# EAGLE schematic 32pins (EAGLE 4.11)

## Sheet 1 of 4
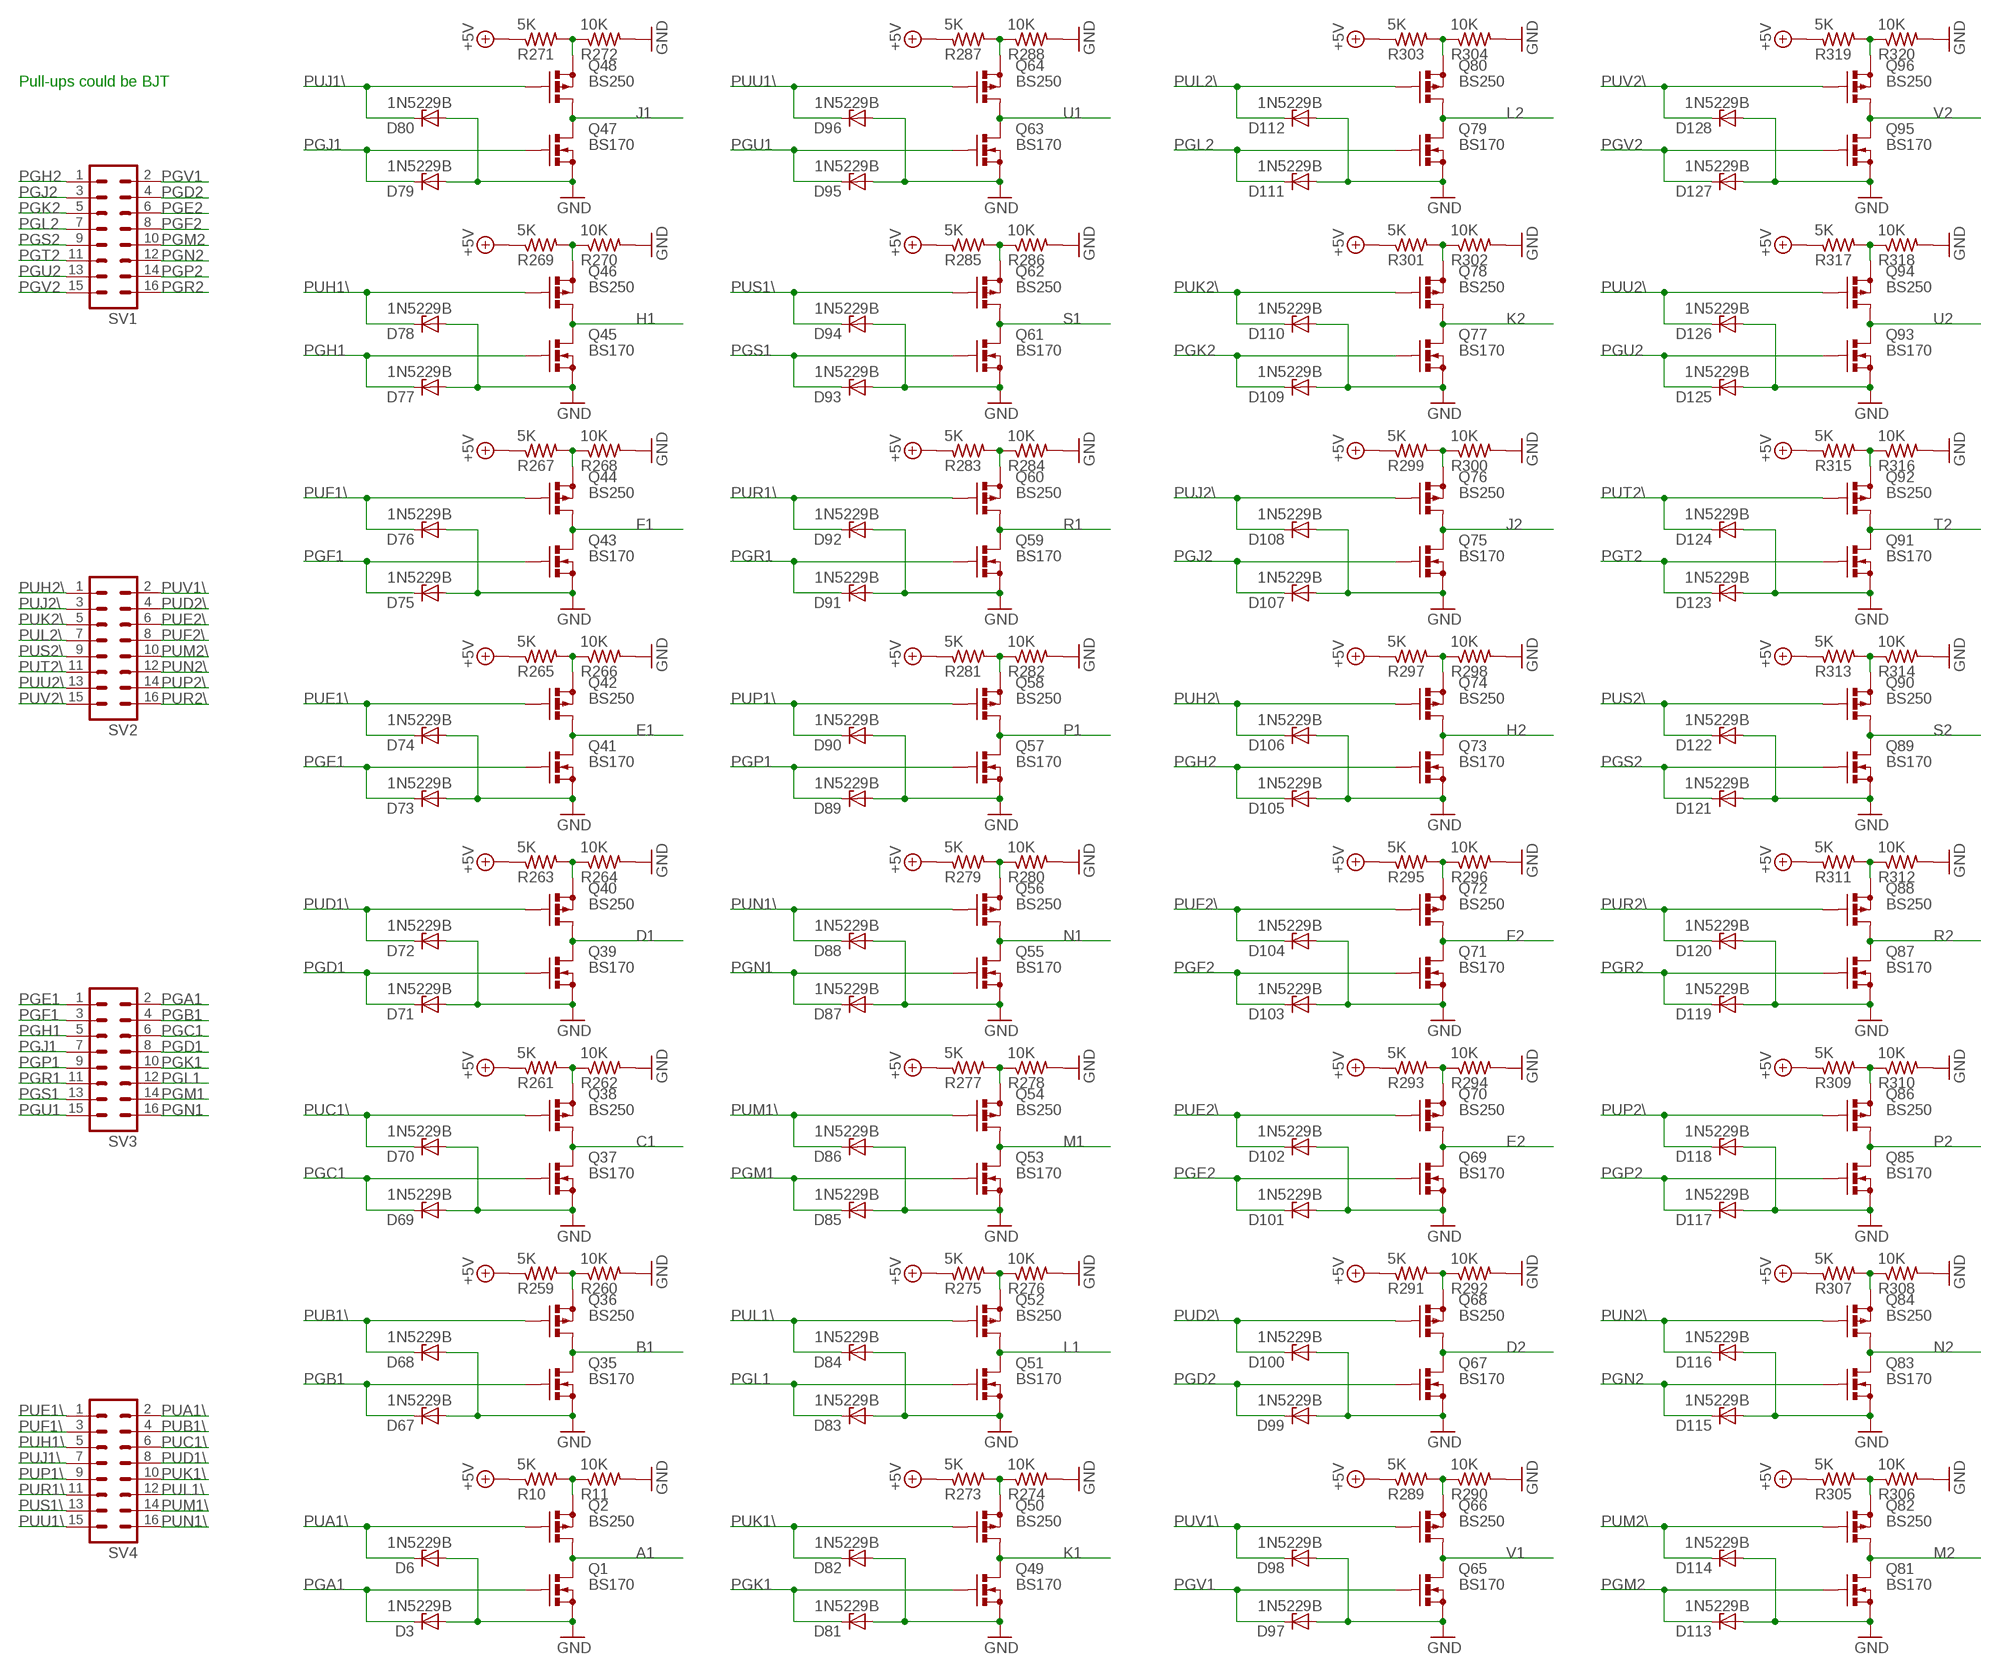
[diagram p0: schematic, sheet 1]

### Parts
D3  1N5229B  ZENER-DIODEZD-2.5  [ZDIO-2.5]
D6  1N5229B  ZENER-DIODEZD-2.5  [ZDIO-2.5]
D67  1N5229B  ZENER-DIODEZD-2.5  [ZDIO-2.5]
D68  1N5229B  ZENER-DIODEZD-2.5  [ZDIO-2.5]
D69  1N5229B  ZENER-DIODEZD-2.5  [ZDIO-2.5]
D70  1N5229B  ZENER-DIODEZD-2.5  [ZDIO-2.5]
D71  1N5229B  ZENER-DIODEZD-2.5  [ZDIO-2.5]
D72  1N5229B  ZENER-DIODEZD-2.5  [ZDIO-2.5]
D73  1N5229B  ZENER-DIODEZD-2.5  [ZDIO-2.5]
D74  1N5229B  ZENER-DIODEZD-2.5  [ZDIO-2.5]
D75  1N5229B  ZENER-DIODEZD-2.5  [ZDIO-2.5]
D76  1N5229B  ZENER-DIODEZD-2.5  [ZDIO-2.5]
D77  1N5229B  ZENER-DIODEZD-2.5  [ZDIO-2.5]
D78  1N5229B  ZENER-DIODEZD-2.5  [ZDIO-2.5]
D79  1N5229B  ZENER-DIODEZD-2.5  [ZDIO-2.5]
D80  1N5229B  ZENER-DIODEZD-2.5  [ZDIO-2.5]
D81  1N5229B  ZENER-DIODEZD-2.5  [ZDIO-2.5]
D82  1N5229B  ZENER-DIODEZD-2.5  [ZDIO-2.5]
D83  1N5229B  ZENER-DIODEZD-2.5  [ZDIO-2.5]
D84  1N5229B  ZENER-DIODEZD-2.5  [ZDIO-2.5]
D85  1N5229B  ZENER-DIODEZD-2.5  [ZDIO-2.5]
D86  1N5229B  ZENER-DIODEZD-2.5  [ZDIO-2.5]
D87  1N5229B  ZENER-DIODEZD-2.5  [ZDIO-2.5]
D88  1N5229B  ZENER-DIODEZD-2.5  [ZDIO-2.5]
D89  1N5229B  ZENER-DIODEZD-2.5  [ZDIO-2.5]
D90  1N5229B  ZENER-DIODEZD-2.5  [ZDIO-2.5]
D91  1N5229B  ZENER-DIODEZD-2.5  [ZDIO-2.5]
D92  1N5229B  ZENER-DIODEZD-2.5  [ZDIO-2.5]
D93  1N5229B  ZENER-DIODEZD-2.5  [ZDIO-2.5]
D94  1N5229B  ZENER-DIODEZD-2.5  [ZDIO-2.5]
D95  1N5229B  ZENER-DIODEZD-2.5  [ZDIO-2.5]
D96  1N5229B  ZENER-DIODEZD-2.5  [ZDIO-2.5]
D97  1N5229B  ZENER-DIODEZD-2.5  [ZDIO-2.5]
D98  1N5229B  ZENER-DIODEZD-2.5  [ZDIO-2.5]
D99  1N5229B  ZENER-DIODEZD-2.5  [ZDIO-2.5]
D100  1N5229B  ZENER-DIODEZD-2.5  [ZDIO-2.5]
D101  1N5229B  ZENER-DIODEZD-2.5  [ZDIO-2.5]
D102  1N5229B  ZENER-DIODEZD-2.5  [ZDIO-2.5]
D103  1N5229B  ZENER-DIODEZD-2.5  [ZDIO-2.5]
D104  1N5229B  ZENER-DIODEZD-2.5  [ZDIO-2.5]
D105  1N5229B  ZENER-DIODEZD-2.5  [ZDIO-2.5]
D106  1N5229B  ZENER-DIODEZD-2.5  [ZDIO-2.5]
D107  1N5229B  ZENER-DIODEZD-2.5  [ZDIO-2.5]
D108  1N5229B  ZENER-DIODEZD-2.5  [ZDIO-2.5]
D109  1N5229B  ZENER-DIODEZD-2.5  [ZDIO-2.5]
D110  1N5229B  ZENER-DIODEZD-2.5  [ZDIO-2.5]
D111  1N5229B  ZENER-DIODEZD-2.5  [ZDIO-2.5]
D112  1N5229B  ZENER-DIODEZD-2.5  [ZDIO-2.5]
D113  1N5229B  ZENER-DIODEZD-2.5  [ZDIO-2.5]
D114  1N5229B  ZENER-DIODEZD-2.5  [ZDIO-2.5]
D115  1N5229B  ZENER-DIODEZD-2.5  [ZDIO-2.5]
D116  1N5229B  ZENER-DIODEZD-2.5  [ZDIO-2.5]
D117  1N5229B  ZENER-DIODEZD-2.5  [ZDIO-2.5]
D118  1N5229B  ZENER-DIODEZD-2.5  [ZDIO-2.5]
D119  1N5229B  ZENER-DIODEZD-2.5  [ZDIO-2.5]
D120  1N5229B  ZENER-DIODEZD-2.5  [ZDIO-2.5]
D121  1N5229B  ZENER-DIODEZD-2.5  [ZDIO-2.5]
D122  1N5229B  ZENER-DIODEZD-2.5  [ZDIO-2.5]
D123  1N5229B  ZENER-DIODEZD-2.5  [ZDIO-2.5]
D124  1N5229B  ZENER-DIODEZD-2.5  [ZDIO-2.5]
D125  1N5229B  ZENER-DIODEZD-2.5  [ZDIO-2.5]
D126  1N5229B  ZENER-DIODEZD-2.5  [ZDIO-2.5]
D127  1N5229B  ZENER-DIODEZD-2.5  [ZDIO-2.5]
D128  1N5229B  ZENER-DIODEZD-2.5  [ZDIO-2.5]
Q1  BS170  [SOT54E]
Q2  BS250  [SOT54E]
Q35  BS170  [SOT54E]
Q36  BS250  [SOT54E]
Q37  BS170  [SOT54E]
Q38  BS250  [SOT54E]
Q39  BS170  [SOT54E]
Q40  BS250  [SOT54E]
Q41  BS170  [SOT54E]
Q42  BS250  [SOT54E]
Q43  BS170  [SOT54E]
Q44  BS250  [SOT54E]
Q45  BS170  [SOT54E]
Q46  BS250  [SOT54E]
Q47  BS170  [SOT54E]
Q48  BS250  [SOT54E]
Q49  BS170  [SOT54E]
Q50  BS250  [SOT54E]
Q51  BS170  [SOT54E]
Q52  BS250  [SOT54E]
Q53  BS170  [SOT54E]
Q54  BS250  [SOT54E]
Q55  BS170  [SOT54E]
Q56  BS250  [SOT54E]
Q57  BS170  [SOT54E]
Q58  BS250  [SOT54E]
Q59  BS170  [SOT54E]
Q60  BS250  [SOT54E]
Q61  BS170  [SOT54E]
Q62  BS250  [SOT54E]
Q63  BS170  [SOT54E]
Q64  BS250  [SOT54E]
Q65  BS170  [SOT54E]
Q66  BS250  [SOT54E]
Q67  BS170  [SOT54E]
Q68  BS250  [SOT54E]
Q69  BS170  [SOT54E]
Q70  BS250  [SOT54E]
Q71  BS170  [SOT54E]
Q72  BS250  [SOT54E]
Q73  BS170  [SOT54E]
Q74  BS250  [SOT54E]
Q75  BS170  [SOT54E]
Q76  BS250  [SOT54E]
Q77  BS170  [SOT54E]
Q78  BS250  [SOT54E]
Q79  BS170  [SOT54E]
Q80  BS250  [SOT54E]
Q81  BS170  [SOT54E]
Q82  BS250  [SOT54E]
Q83  BS170  [SOT54E]
Q84  BS250  [SOT54E]
Q85  BS170  [SOT54E]
Q86  BS250  [SOT54E]
Q87  BS170  [SOT54E]
Q88  BS250  [SOT54E]
Q89  BS170  [SOT54E]
Q90  BS250  [SOT54E]
Q91  BS170  [SOT54E]
Q92  BS250  [SOT54E]
Q93  BS170  [SOT54E]
Q94  BS250  [SOT54E]
Q95  BS170  [SOT54E]
Q96  BS250  [SOT54E]
R10  5K  R-US_0207/2V  [0207/2V]
R11  10K  R-US_0207/2V  [0207/2V]
R259  5K  R-US_0207/2V  [0207/2V]
R260  10K  R-US_0207/2V  [0207/2V]
R261  5K  R-US_0207/2V  [0207/2V]
R262  10K  R-US_0207/2V  [0207/2V]
R263  5K  R-US_0207/2V  [0207/2V]
R264  10K  R-US_0207/2V  [0207/2V]
R265  5K  R-US_0207/2V  [0207/2V]
R266  10K  R-US_0207/2V  [0207/2V]
R267  5K  R-US_0207/2V  [0207/2V]
R268  10K  R-US_0207/2V  [0207/2V]
R269  5K  R-US_0207/2V  [0207/2V]
R270  10K  R-US_0207/2V  [0207/2V]
R271  5K  R-US_0207/2V  [0207/2V]
R272  10K  R-US_0207/2V  [0207/2V]
R273  5K  R-US_0207/2V  [0207/2V]
R274  10K  R-US_0207/2V  [0207/2V]
R275  5K  R-US_0207/2V  [0207/2V]
R276  10K  R-US_0207/2V  [0207/2V]
R277  5K  R-US_0207/2V  [0207/2V]
R278  10K  R-US_0207/2V  [0207/2V]
R279  5K  R-US_0207/2V  [0207/2V]
R280  10K  R-US_0207/2V  [0207/2V]
R281  5K  R-US_0207/2V  [0207/2V]
R282  10K  R-US_0207/2V  [0207/2V]
R283  5K  R-US_0207/2V  [0207/2V]
R284  10K  R-US_0207/2V  [0207/2V]
R285  5K  R-US_0207/2V  [0207/2V]
R286  10K  R-US_0207/2V  [0207/2V]
R287  5K  R-US_0207/2V  [0207/2V]
R288  10K  R-US_0207/2V  [0207/2V]
R289  5K  R-US_0207/2V  [0207/2V]
R290  10K  R-US_0207/2V  [0207/2V]
R291  5K  R-US_0207/2V  [0207/2V]
R292  10K  R-US_0207/2V  [0207/2V]
R293  5K  R-US_0207/2V  [0207/2V]
R294  10K  R-US_0207/2V  [0207/2V]
R295  5K  R-US_0207/2V  [0207/2V]
R296  10K  R-US_0207/2V  [0207/2V]
R297  5K  R-US_0207/2V  [0207/2V]
R298  10K  R-US_0207/2V  [0207/2V]
R299  5K  R-US_0207/2V  [0207/2V]
R300  10K  R-US_0207/2V  [0207/2V]
R301  5K  R-US_0207/2V  [0207/2V]
R302  10K  R-US_0207/2V  [0207/2V]
R303  5K  R-US_0207/2V  [0207/2V]
R304  10K  R-US_0207/2V  [0207/2V]
R305  5K  R-US_0207/2V  [0207/2V]
R306  10K  R-US_0207/2V  [0207/2V]
R307  5K  R-US_0207/2V  [0207/2V]
R308  10K  R-US_0207/2V  [0207/2V]
R309  5K  R-US_0207/2V  [0207/2V]
R310  10K  R-US_0207/2V  [0207/2V]
R311  5K  R-US_0207/2V  [0207/2V]
R312  10K  R-US_0207/2V  [0207/2V]
R313  5K  R-US_0207/2V  [0207/2V]
R314  10K  R-US_0207/2V  [0207/2V]
R315  5K  R-US_0207/2V  [0207/2V]
R316  10K  R-US_0207/2V  [0207/2V]
R317  5K  R-US_0207/2V  [0207/2V]
R318  10K  R-US_0207/2V  [0207/2V]
R319  5K  R-US_0207/2V  [0207/2V]
R320  10K  R-US_0207/2V  [0207/2V]
SV1  MA08-2  [MA08-2]
SV2  MA08-2  [MA08-2]
SV3  MA08-2  [MA08-2]
SV4  MA08-2  [MA08-2]

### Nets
+5V: R10.1 R259.1 R261.1 R263.1 R265.1 R267.1 R269.1 R271.1 R273.1 R275.1 R277.1 R279.1 R281.1 R283.1 R285.1 R287.1 R289.1 R291.1 R293.1 R295.1 R297.1 R299.1 R301.1 R303.1 R305.1 R307.1 R309.1 R311.1 R313.1 R315.1 R317.1 R319.1 ; also sheet 4
A1: Q1.D Q2.D ; also sheet 2,3,4
B1: Q35.D Q36.D ; also sheet 2,3,4
C1: Q37.D Q38.D ; also sheet 2,3,4
D1: Q39.D Q40.D ; also sheet 2,3,4
D2: Q67.D Q68.D ; also sheet 2,3,4
E1: Q41.D Q42.D ; also sheet 2,3,4
E2: Q69.D Q70.D ; also sheet 2,3,4
F1: Q43.D Q44.D ; also sheet 2,3,4
F2: Q71.D Q72.D ; also sheet 2,3,4
GND: D3.A D6.A D67.A D68.A D69.A D70.A D71.A D72.A D73.A D74.A D75.A D76.A D77.A D78.A D79.A D80.A D81.A D82.A D83.A D84.A D85.A D86.A D87.A D88.A D89.A D90.A D91.A D92.A D93.A D94.A D95.A D96.A D97.A D98.A D99.A D100.A D101.A D102.A D103.A D104.A D105.A D106.A D107.A D108.A D109.A D110.A D111.A D112.A D113.A D114.A D115.A D116.A D117.A D118.A D119.A D120.A D121.A D122.A D123.A D124.A D125.A D126.A D127.A D128.A Q1.S Q35.S Q37.S Q39.S Q41.S Q43.S Q45.S Q47.S Q49.S Q51.S Q53.S Q55.S Q57.S Q59.S Q61.S Q63.S Q65.S Q67.S Q69.S Q71.S Q73.S Q75.S Q77.S Q79.S Q81.S Q83.S Q85.S Q87.S Q89.S Q91.S Q93.S Q95.S R11.2 R260.2 R262.2 R264.2 R266.2 R268.2 R270.2 R272.2 R274.2 R276.2 R278.2 R280.2 R282.2 R284.2 R286.2 R288.2 R290.2 R292.2 R294.2 R296.2 R298.2 R300.2 R302.2 R304.2 R306.2 R308.2 R310.2 R312.2 R314.2 R316.2 R318.2 R320.2 ; also sheet 2,3,4
H1: Q45.D Q46.D ; also sheet 2,3,4
H2: Q73.D Q74.D ; also sheet 2,3,4
J1: Q47.D Q48.D ; also sheet 2,3,4
J2: Q75.D Q76.D ; also sheet 2,3,4
K1: Q49.D Q50.D ; also sheet 2,3,4
K2: Q77.D Q78.D ; also sheet 2,3,4
L1: Q51.D Q52.D ; also sheet 2,3,4
L2: Q79.D Q80.D ; also sheet 2,3,4
M1: Q53.D Q54.D ; also sheet 2,3,4
M2: Q81.D Q82.D ; also sheet 2,3,4
N1: Q55.D Q56.D ; also sheet 2,3,4
N2: Q83.D Q84.D ; also sheet 2,3,4
N$5: Q2.S R10.2 R11.1
N$294: Q36.S R259.2 R260.1
N$298: Q38.S R261.2 R262.1
N$302: Q40.S R263.2 R264.1
N$306: Q42.S R265.2 R266.1
N$310: Q44.S R267.2 R268.1
N$314: Q46.S R269.2 R270.1
N$318: Q48.S R271.2 R272.1
N$322: Q50.S R273.2 R274.1
N$326: Q52.S R275.2 R276.1
N$330: Q54.S R277.2 R278.1
N$334: Q56.S R279.2 R280.1
N$338: Q58.S R281.2 R282.1
N$342: Q60.S R283.2 R284.1
N$346: Q62.S R285.2 R286.1
N$350: Q64.S R287.2 R288.1
N$354: Q66.S R289.2 R290.1
N$358: Q68.S R291.2 R292.1
N$362: Q70.S R293.2 R294.1
N$366: Q72.S R295.2 R296.1
N$370: Q74.S R297.2 R298.1
N$374: Q76.S R299.2 R300.1
N$378: Q78.S R301.2 R302.1
N$382: Q80.S R303.2 R304.1
N$386: Q82.S R305.2 R306.1
N$390: Q84.S R307.2 R308.1
N$394: Q86.S R309.2 R310.1
N$398: Q88.S R311.2 R312.1
N$402: Q90.S R313.2 R314.1
N$406: Q92.S R315.2 R316.1
N$410: Q94.S R317.2 R318.1
N$414: Q96.S R319.2 R320.1
P1: Q57.D Q58.D ; also sheet 2,3,4
P2: Q85.D Q86.D ; also sheet 2,3,4
PGA1: D3.C Q1.G SV3.2
PGB1: D67.C Q35.G SV3.4
PGC1: D69.C Q37.G SV3.6
PGD1: D71.C Q39.G SV3.8
PGD2: D99.C Q67.G SV1.4
PGE1: D73.C Q41.G SV3.1
PGE2: D101.C Q69.G SV1.6
PGF1: D75.C Q43.G SV3.3
PGF2: D103.C Q71.G SV1.8
PGH1: D77.C Q45.G SV3.5
PGH2: D105.C Q73.G SV1.1
PGJ1: D79.C Q47.G SV3.7
PGJ2: D107.C Q75.G SV1.3
PGK1: D81.C Q49.G SV3.10
PGK2: D109.C Q77.G SV1.5
PGL1: D83.C Q51.G SV3.12
PGL2: D111.C Q79.G SV1.7
PGM1: D85.C Q53.G SV3.14
PGM2: D113.C Q81.G SV1.10
PGN1: D87.C Q55.G SV3.16
PGN2: D115.C Q83.G SV1.12
PGP1: D89.C Q57.G SV3.9
PGP2: D117.C Q85.G SV1.14
PGR1: D91.C Q59.G SV3.11
PGR2: D119.C Q87.G SV1.16
PGS1: D93.C Q61.G SV3.13
PGS2: D121.C Q89.G SV1.9
PGT2: D123.C Q91.G SV1.11
PGU1: D95.C Q63.G SV3.15
PGU2: D125.C Q93.G SV1.13
PGV1: D97.C Q65.G SV1.2
PGV2: D127.C Q95.G SV1.15
PUA1\: D6.C Q2.G SV4.2
PUB1\: D68.C Q36.G SV4.4
PUC1\: D70.C Q38.G SV4.6
PUD1\: D72.C Q40.G SV4.8
PUD2\: D100.C Q68.G SV2.4
PUE1\: D74.C Q42.G SV4.1
PUE2\: D102.C Q70.G SV2.6
PUF1\: D76.C Q44.G SV4.3
PUF2\: D104.C Q72.G SV2.8
PUH1\: D78.C Q46.G SV4.5
PUH2\: D106.C Q74.G SV2.1
PUJ1\: D80.C Q48.G SV4.7
PUJ2\: D108.C Q76.G SV2.3
PUK1\: D82.C Q50.G SV4.10
PUK2\: D110.C Q78.G SV2.5
PUL1\: D84.C Q52.G SV4.12
PUL2\: D112.C Q80.G SV2.7
PUM1\: D86.C Q54.G SV4.14
PUM2\: D114.C Q82.G SV2.10
PUN1\: D88.C Q56.G SV4.16
PUN2\: D116.C Q84.G SV2.12
PUP1\: D90.C Q58.G SV4.9
PUP2\: D118.C Q86.G SV2.14
PUR1\: D92.C Q60.G SV4.11
PUR2\: D120.C Q88.G SV2.16
PUS1\: D94.C Q62.G SV4.13
PUS2\: D122.C Q90.G SV2.9
PUT2\: D124.C Q92.G SV2.11
PUU1\: D96.C Q64.G SV4.15
PUU2\: D126.C Q94.G SV2.13
PUV1\: D98.C Q66.G SV2.2
PUV2\: D128.C Q96.G SV2.15
R1: Q59.D Q60.D ; also sheet 2,3,4
R2: Q87.D Q88.D ; also sheet 2,3,4
S1: Q61.D Q62.D ; also sheet 2,3,4
S2: Q89.D Q90.D ; also sheet 2,3,4
T2: Q91.D Q92.D ; also sheet 2,3,4
U1: Q63.D Q64.D ; also sheet 2,3,4
U2: Q93.D Q94.D ; also sheet 2,3,4
V1: Q65.D Q66.D ; also sheet 2,3,4
V2: Q95.D Q96.D ; also sheet 2,3,4

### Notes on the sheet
- Pull-ups could be BJT

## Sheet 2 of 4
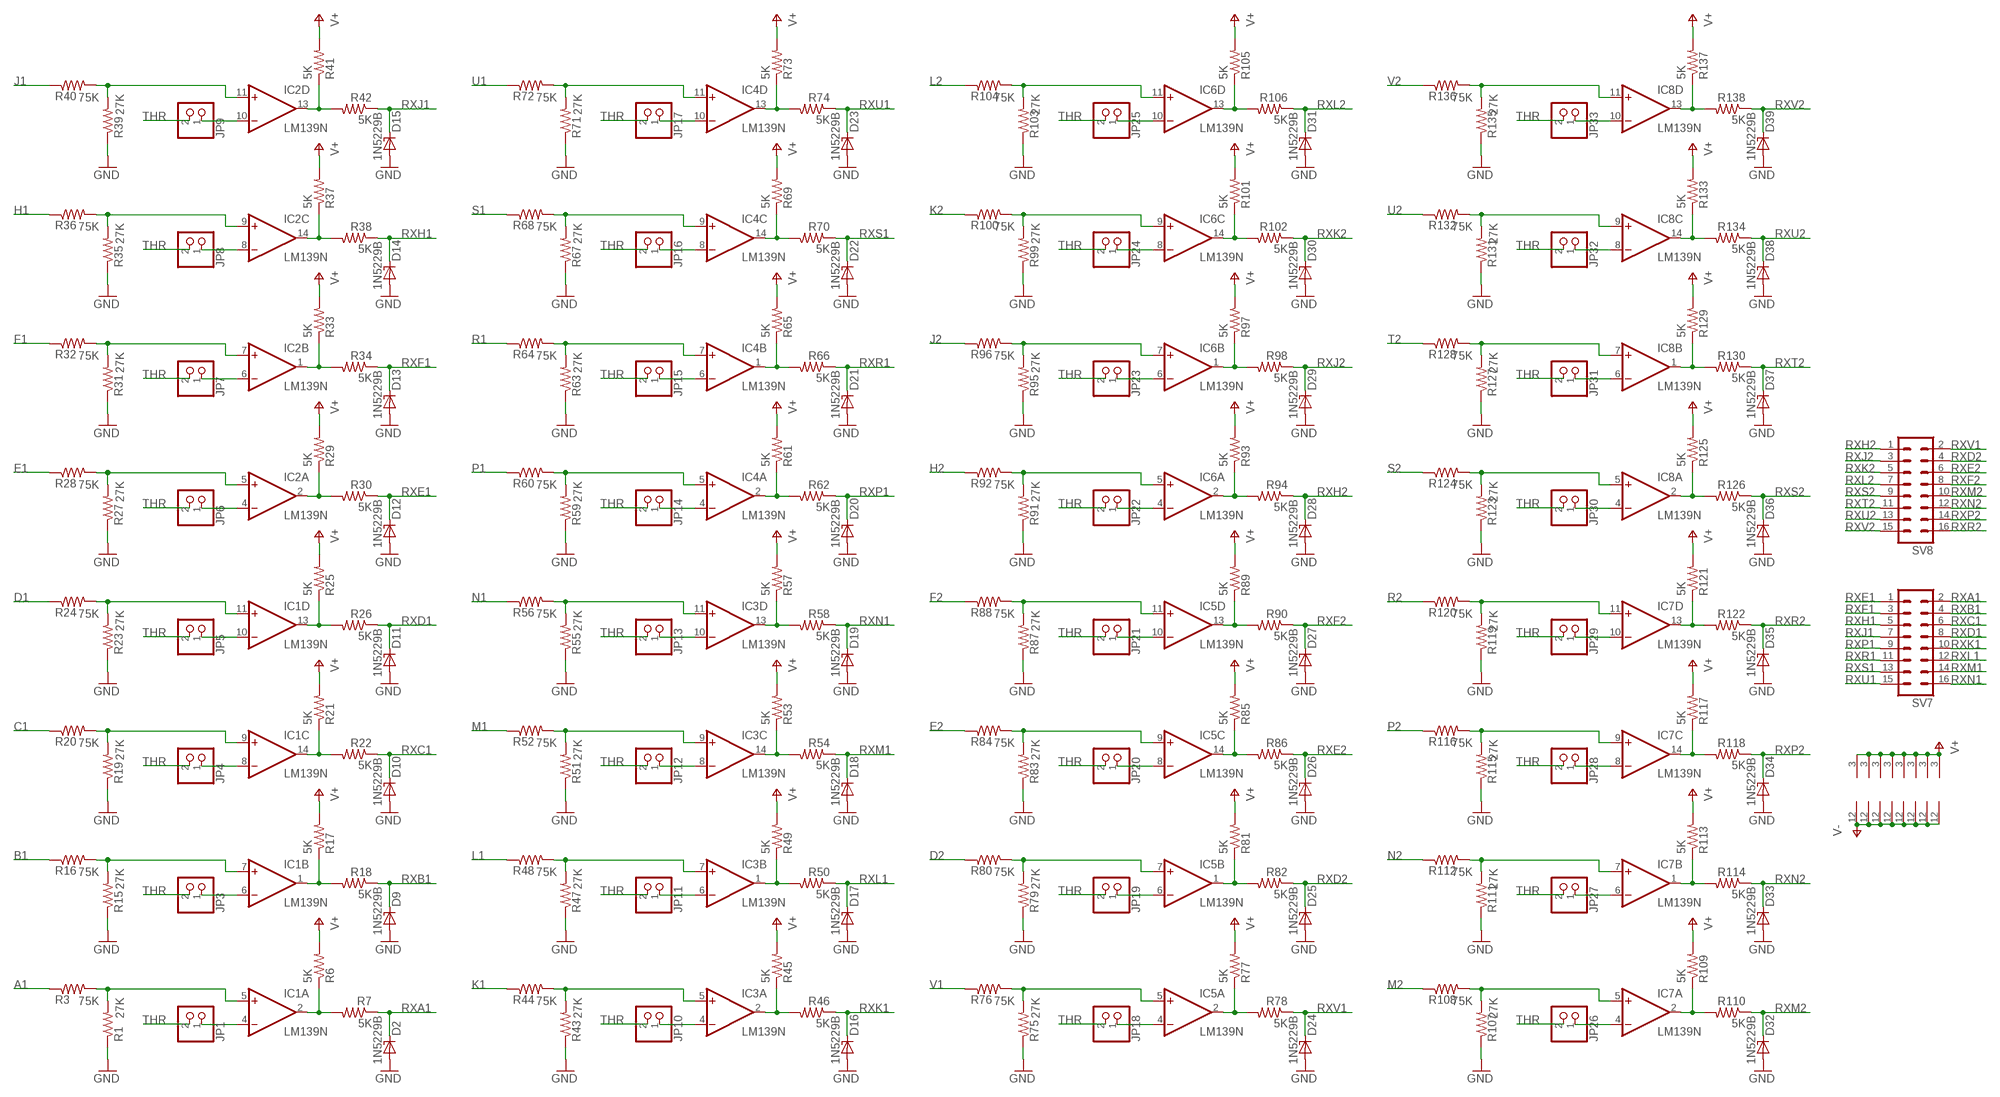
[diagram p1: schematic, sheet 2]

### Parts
D2  1N5229B  ZENER-DIODEZD-2.5  [ZDIO-2.5]
D9  1N5229B  ZENER-DIODEZD-2.5  [ZDIO-2.5]
D10  1N5229B  ZENER-DIODEZD-2.5  [ZDIO-2.5]
D11  1N5229B  ZENER-DIODEZD-2.5  [ZDIO-2.5]
D12  1N5229B  ZENER-DIODEZD-2.5  [ZDIO-2.5]
D13  1N5229B  ZENER-DIODEZD-2.5  [ZDIO-2.5]
D14  1N5229B  ZENER-DIODEZD-2.5  [ZDIO-2.5]
D15  1N5229B  ZENER-DIODEZD-2.5  [ZDIO-2.5]
D16  1N5229B  ZENER-DIODEZD-2.5  [ZDIO-2.5]
D17  1N5229B  ZENER-DIODEZD-2.5  [ZDIO-2.5]
D18  1N5229B  ZENER-DIODEZD-2.5  [ZDIO-2.5]
D19  1N5229B  ZENER-DIODEZD-2.5  [ZDIO-2.5]
D20  1N5229B  ZENER-DIODEZD-2.5  [ZDIO-2.5]
D21  1N5229B  ZENER-DIODEZD-2.5  [ZDIO-2.5]
D22  1N5229B  ZENER-DIODEZD-2.5  [ZDIO-2.5]
D23  1N5229B  ZENER-DIODEZD-2.5  [ZDIO-2.5]
D24  1N5229B  ZENER-DIODEZD-2.5  [ZDIO-2.5]
D25  1N5229B  ZENER-DIODEZD-2.5  [ZDIO-2.5]
D26  1N5229B  ZENER-DIODEZD-2.5  [ZDIO-2.5]
D27  1N5229B  ZENER-DIODEZD-2.5  [ZDIO-2.5]
D28  1N5229B  ZENER-DIODEZD-2.5  [ZDIO-2.5]
D29  1N5229B  ZENER-DIODEZD-2.5  [ZDIO-2.5]
D30  1N5229B  ZENER-DIODEZD-2.5  [ZDIO-2.5]
D31  1N5229B  ZENER-DIODEZD-2.5  [ZDIO-2.5]
D32  1N5229B  ZENER-DIODEZD-2.5  [ZDIO-2.5]
D33  1N5229B  ZENER-DIODEZD-2.5  [ZDIO-2.5]
D34  1N5229B  ZENER-DIODEZD-2.5  [ZDIO-2.5]
D35  1N5229B  ZENER-DIODEZD-2.5  [ZDIO-2.5]
D36  1N5229B  ZENER-DIODEZD-2.5  [ZDIO-2.5]
D37  1N5229B  ZENER-DIODEZD-2.5  [ZDIO-2.5]
D38  1N5229B  ZENER-DIODEZD-2.5  [ZDIO-2.5]
D39  1N5229B  ZENER-DIODEZD-2.5  [ZDIO-2.5]
IC1  LM139N  LM339N  [DIL14]
IC2  LM139N  LM339N  [DIL14]
IC3  LM139N  LM339N  [DIL14]
IC4  LM139N  LM339N  [DIL14]
IC5  LM139N  LM339N  [DIL14]
IC6  LM139N  LM339N  [DIL14]
IC7  LM139N  LM339N  [DIL14]
IC8  LM139N  LM339N  [DIL14]
JP1  PINHD-1X2  [1X02]
JP3  PINHD-1X2  [1X02]
JP4  PINHD-1X2  [1X02]
JP5  PINHD-1X2  [1X02]
JP6  PINHD-1X2  [1X02]
JP7  PINHD-1X2  [1X02]
JP8  PINHD-1X2  [1X02]
JP9  PINHD-1X2  [1X02]
JP10  PINHD-1X2  [1X02]
JP11  PINHD-1X2  [1X02]
JP12  PINHD-1X2  [1X02]
JP13  PINHD-1X2  [1X02]
JP14  PINHD-1X2  [1X02]
JP15  PINHD-1X2  [1X02]
JP16  PINHD-1X2  [1X02]
JP17  PINHD-1X2  [1X02]
JP18  PINHD-1X2  [1X02]
JP19  PINHD-1X2  [1X02]
JP20  PINHD-1X2  [1X02]
JP21  PINHD-1X2  [1X02]
JP22  PINHD-1X2  [1X02]
JP23  PINHD-1X2  [1X02]
JP24  PINHD-1X2  [1X02]
JP25  PINHD-1X2  [1X02]
JP26  PINHD-1X2  [1X02]
JP27  PINHD-1X2  [1X02]
JP28  PINHD-1X2  [1X02]
JP29  PINHD-1X2  [1X02]
JP30  PINHD-1X2  [1X02]
JP31  PINHD-1X2  [1X02]
JP32  PINHD-1X2  [1X02]
JP33  PINHD-1X2  [1X02]
R1  27K  R-US_0207/2V  [0207/2V]
R3  75K  R-US_0207/2V  [0207/2V]
R6  5K  R-US_0207/2V  [0207/2V]
R7  5K  R-US_0207/2V  [0207/2V]
R15  27K  R-US_0207/2V  [0207/2V]
R16  75K  R-US_0207/2V  [0207/2V]
R17  5K  R-US_0207/2V  [0207/2V]
R18  5K  R-US_0207/2V  [0207/2V]
R19  27K  R-US_0207/2V  [0207/2V]
R20  75K  R-US_0207/2V  [0207/2V]
R21  5K  R-US_0207/2V  [0207/2V]
R22  5K  R-US_0207/2V  [0207/2V]
R23  27K  R-US_0207/2V  [0207/2V]
R24  75K  R-US_0207/2V  [0207/2V]
R25  5K  R-US_0207/2V  [0207/2V]
R26  5K  R-US_0207/2V  [0207/2V]
R27  27K  R-US_0207/2V  [0207/2V]
R28  75K  R-US_0207/2V  [0207/2V]
R29  5K  R-US_0207/2V  [0207/2V]
R30  5K  R-US_0207/2V  [0207/2V]
R31  27K  R-US_0207/2V  [0207/2V]
R32  75K  R-US_0207/2V  [0207/2V]
R33  5K  R-US_0207/2V  [0207/2V]
R34  5K  R-US_0207/2V  [0207/2V]
R35  27K  R-US_0207/2V  [0207/2V]
R36  75K  R-US_0207/2V  [0207/2V]
R37  5K  R-US_0207/2V  [0207/2V]
R38  5K  R-US_0207/2V  [0207/2V]
R39  27K  R-US_0207/2V  [0207/2V]
R40  75K  R-US_0207/2V  [0207/2V]
R41  5K  R-US_0207/2V  [0207/2V]
R42  5K  R-US_0207/2V  [0207/2V]
R43  27K  R-US_0207/2V  [0207/2V]
R44  75K  R-US_0207/2V  [0207/2V]
R45  5K  R-US_0207/2V  [0207/2V]
R46  5K  R-US_0207/2V  [0207/2V]
R47  27K  R-US_0207/2V  [0207/2V]
R48  75K  R-US_0207/2V  [0207/2V]
R49  5K  R-US_0207/2V  [0207/2V]
R50  5K  R-US_0207/2V  [0207/2V]
R51  27K  R-US_0207/2V  [0207/2V]
R52  75K  R-US_0207/2V  [0207/2V]
R53  5K  R-US_0207/2V  [0207/2V]
R54  5K  R-US_0207/2V  [0207/2V]
R55  27K  R-US_0207/2V  [0207/2V]
R56  75K  R-US_0207/2V  [0207/2V]
R57  5K  R-US_0207/2V  [0207/2V]
R58  5K  R-US_0207/2V  [0207/2V]
R59  27K  R-US_0207/2V  [0207/2V]
R60  75K  R-US_0207/2V  [0207/2V]
R61  5K  R-US_0207/2V  [0207/2V]
R62  5K  R-US_0207/2V  [0207/2V]
R63  27K  R-US_0207/2V  [0207/2V]
R64  75K  R-US_0207/2V  [0207/2V]
R65  5K  R-US_0207/2V  [0207/2V]
R66  5K  R-US_0207/2V  [0207/2V]
R67  27K  R-US_0207/2V  [0207/2V]
R68  75K  R-US_0207/2V  [0207/2V]
R69  5K  R-US_0207/2V  [0207/2V]
R70  5K  R-US_0207/2V  [0207/2V]
R71  27K  R-US_0207/2V  [0207/2V]
R72  75K  R-US_0207/2V  [0207/2V]
R73  5K  R-US_0207/2V  [0207/2V]
R74  5K  R-US_0207/2V  [0207/2V]
R75  27K  R-US_0207/2V  [0207/2V]
R76  75K  R-US_0207/2V  [0207/2V]
R77  5K  R-US_0207/2V  [0207/2V]
R78  5K  R-US_0207/2V  [0207/2V]
R79  27K  R-US_0207/2V  [0207/2V]
R80  75K  R-US_0207/2V  [0207/2V]
R81  5K  R-US_0207/2V  [0207/2V]
R82  5K  R-US_0207/2V  [0207/2V]
R83  27K  R-US_0207/2V  [0207/2V]
R84  75K  R-US_0207/2V  [0207/2V]
R85  5K  R-US_0207/2V  [0207/2V]
R86  5K  R-US_0207/2V  [0207/2V]
R87  27K  R-US_0207/2V  [0207/2V]
R88  75K  R-US_0207/2V  [0207/2V]
R89  5K  R-US_0207/2V  [0207/2V]
R90  5K  R-US_0207/2V  [0207/2V]
R91  27K  R-US_0207/2V  [0207/2V]
R92  75K  R-US_0207/2V  [0207/2V]
R93  5K  R-US_0207/2V  [0207/2V]
R94  5K  R-US_0207/2V  [0207/2V]
R95  27K  R-US_0207/2V  [0207/2V]
R96  75K  R-US_0207/2V  [0207/2V]
R97  5K  R-US_0207/2V  [0207/2V]
R98  5K  R-US_0207/2V  [0207/2V]
R99  27K  R-US_0207/2V  [0207/2V]
R100  75K  R-US_0207/2V  [0207/2V]
R101  5K  R-US_0207/2V  [0207/2V]
R102  5K  R-US_0207/2V  [0207/2V]
R103  27K  R-US_0207/2V  [0207/2V]
R104  75K  R-US_0207/2V  [0207/2V]
R105  5K  R-US_0207/2V  [0207/2V]
R106  5K  R-US_0207/2V  [0207/2V]
R107  27K  R-US_0207/2V  [0207/2V]
R108  75K  R-US_0207/2V  [0207/2V]
R109  5K  R-US_0207/2V  [0207/2V]
R110  5K  R-US_0207/2V  [0207/2V]
R111  27K  R-US_0207/2V  [0207/2V]
R112  75K  R-US_0207/2V  [0207/2V]
R113  5K  R-US_0207/2V  [0207/2V]
R114  5K  R-US_0207/2V  [0207/2V]
R115  27K  R-US_0207/2V  [0207/2V]
R116  75K  R-US_0207/2V  [0207/2V]
R117  5K  R-US_0207/2V  [0207/2V]
R118  5K  R-US_0207/2V  [0207/2V]
R119  27K  R-US_0207/2V  [0207/2V]
R120  75K  R-US_0207/2V  [0207/2V]
R121  5K  R-US_0207/2V  [0207/2V]
R122  5K  R-US_0207/2V  [0207/2V]
R123  27K  R-US_0207/2V  [0207/2V]
R124  75K  R-US_0207/2V  [0207/2V]
R125  5K  R-US_0207/2V  [0207/2V]
R126  5K  R-US_0207/2V  [0207/2V]
R127  27K  R-US_0207/2V  [0207/2V]
R128  75K  R-US_0207/2V  [0207/2V]
R129  5K  R-US_0207/2V  [0207/2V]
R130  5K  R-US_0207/2V  [0207/2V]
R131  27K  R-US_0207/2V  [0207/2V]
R132  75K  R-US_0207/2V  [0207/2V]
R133  5K  R-US_0207/2V  [0207/2V]
R134  5K  R-US_0207/2V  [0207/2V]
R135  27K  R-US_0207/2V  [0207/2V]
R136  75K  R-US_0207/2V  [0207/2V]
R137  5K  R-US_0207/2V  [0207/2V]
R138  5K  R-US_0207/2V  [0207/2V]
SV7  MA08-2  [MA08-2]
SV8  MA08-2  [MA08-2]

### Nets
A1: R3.1 ; also sheet 1,3,4
B1: R16.1 ; also sheet 1,3,4
C1: R20.1 ; also sheet 1,3,4
D1: R24.1 ; also sheet 1,3,4
D2: R80.1 ; also sheet 1,3,4
E1: R28.1 ; also sheet 1,3,4
E2: R84.1 ; also sheet 1,3,4
F1: R32.1 ; also sheet 1,3,4
F2: R88.1 ; also sheet 1,3,4
GND: D2.A D9.A D10.A D11.A D12.A D13.A D14.A D15.A D16.A D17.A D18.A D19.A D20.A D21.A D22.A D23.A D24.A D25.A D26.A D27.A D28.A D29.A D30.A D31.A D32.A D33.A D34.A D35.A D36.A D37.A D38.A D39.A R1.1 R15.1 R19.1 R23.1 R27.1 R31.1 R35.1 R39.1 R43.1 R47.1 R51.1 R55.1 R59.1 R63.1 R67.1 R71.1 R75.1 R79.1 R83.1 R87.1 R91.1 R95.1 R99.1 R103.1 R107.1 R111.1 R115.1 R119.1 R123.1 R127.1 R131.1 R135.1 ; also sheet 1,3,4
H1: R36.1 ; also sheet 1,3,4
H2: R92.1 ; also sheet 1,3,4
J1: R40.1 ; also sheet 1,3,4
J2: R96.1 ; also sheet 1,3,4
K1: R44.1 ; also sheet 1,3,4
K2: R100.1 ; also sheet 1,3,4
L1: R48.1 ; also sheet 1,3,4
L2: R104.1 ; also sheet 1,3,4
M1: R52.1 ; also sheet 1,3,4
M2: R108.1 ; also sheet 1,3,4
N1: R56.1 ; also sheet 1,3,4
N2: R112.1 ; also sheet 1,3,4
N$13: IC1.5(A:+IN) R1.2 R3.2
N$14: IC1.4(A:-IN) JP1.1
N$18: IC1.2(A:OUT) R6.1 R7.2
N$20: IC1.7(B:+IN) R15.2 R16.2
N$21: IC1.6(B:-IN) JP3.1
N$22: IC1.1(B:OUT) R17.1 R18.2
N$23: IC1.9(C:+IN) R19.2 R20.2
N$24: IC1.8(C:-IN) JP4.1
N$25: IC1.14(C:OUT) R21.1 R22.2
N$26: IC1.11(D:+IN) R23.2 R24.2
N$27: IC1.10(D:-IN) JP5.1
N$28: IC1.13(D:OUT) R25.1 R26.2
N$35: IC2.5(A:+IN) R27.2 R28.2
N$36: IC2.4(A:-IN) JP6.1
N$38: IC2.2(A:OUT) R29.1 R30.2
N$39: IC2.7(B:+IN) R31.2 R32.2
N$40: IC2.6(B:-IN) JP7.1
N$41: IC2.1(B:OUT) R33.1 R34.2
N$42: IC2.9(C:+IN) R35.2 R36.2
N$43: IC2.8(C:-IN) JP8.1
N$44: IC2.14(C:OUT) R37.1 R38.2
N$45: IC2.11(D:+IN) R39.2 R40.2
N$46: IC2.10(D:-IN) JP9.1
N$47: IC2.13(D:OUT) R41.1 R42.2
N$55: IC3.5(A:+IN) R43.2 R44.2
N$56: IC3.4(A:-IN) JP10.1
N$58: IC3.2(A:OUT) R45.1 R46.2
N$59: IC3.7(B:+IN) R47.2 R48.2
N$60: IC3.6(B:-IN) JP11.1
N$61: IC3.1(B:OUT) R49.1 R50.2
N$62: IC3.9(C:+IN) R51.2 R52.2
N$63: IC3.8(C:-IN) JP12.1
N$64: IC3.14(C:OUT) R53.1 R54.2
N$65: IC3.11(D:+IN) R55.2 R56.2
N$66: IC3.10(D:-IN) JP13.1
N$67: IC3.13(D:OUT) R57.1 R58.2
N$75: IC4.5(A:+IN) R59.2 R60.2
N$76: IC4.4(A:-IN) JP14.1
N$78: IC4.2(A:OUT) R61.1 R62.2
N$79: IC4.7(B:+IN) R63.2 R64.2
N$80: IC4.6(B:-IN) JP15.1
N$81: IC4.1(B:OUT) R65.1 R66.2
N$82: IC4.9(C:+IN) R67.2 R68.2
N$83: IC4.8(C:-IN) JP16.1
N$84: IC4.14(C:OUT) R69.1 R70.2
N$85: IC4.11(D:+IN) R71.2 R72.2
N$86: IC4.10(D:-IN) JP17.1
N$87: IC4.13(D:OUT) R73.1 R74.2
N$95: IC5.5(A:+IN) R75.2 R76.2
N$96: IC5.4(A:-IN) JP18.1
N$98: IC5.2(A:OUT) R77.1 R78.2
N$99: IC5.7(B:+IN) R79.2 R80.2
N$100: IC5.6(B:-IN) JP19.1
N$101: IC5.1(B:OUT) R81.1 R82.2
N$102: IC5.9(C:+IN) R83.2 R84.2
N$103: IC5.8(C:-IN) JP20.1
N$104: IC5.14(C:OUT) R85.1 R86.2
N$105: IC5.11(D:+IN) R87.2 R88.2
N$106: IC5.10(D:-IN) JP21.1
N$107: IC5.13(D:OUT) R89.1 R90.2
N$115: IC6.5(A:+IN) R91.2 R92.2
N$116: IC6.4(A:-IN) JP22.1
N$118: IC6.2(A:OUT) R93.1 R94.2
N$119: IC6.7(B:+IN) R95.2 R96.2
N$120: IC6.6(B:-IN) JP23.1
N$121: IC6.1(B:OUT) R97.1 R98.2
N$122: IC6.9(C:+IN) R99.2 R100.2
N$123: IC6.8(C:-IN) JP24.1
N$124: IC6.14(C:OUT) R101.1 R102.2
N$125: IC6.11(D:+IN) R103.2 R104.2
N$126: IC6.10(D:-IN) JP25.1
N$127: IC6.13(D:OUT) R105.1 R106.2
N$135: IC7.5(A:+IN) R107.2 R108.2
N$136: IC7.4(A:-IN) JP26.1
N$138: IC7.2(A:OUT) R109.1 R110.2
N$139: IC7.7(B:+IN) R111.2 R112.2
N$140: IC7.6(B:-IN) JP27.1
N$141: IC7.1(B:OUT) R113.1 R114.2
N$142: IC7.9(C:+IN) R115.2 R116.2
N$143: IC7.8(C:-IN) JP28.1
N$144: IC7.14(C:OUT) R117.1 R118.2
N$145: IC7.11(D:+IN) R119.2 R120.2
N$146: IC7.10(D:-IN) JP29.1
N$147: IC7.13(D:OUT) R121.1 R122.2
N$155: IC8.5(A:+IN) R123.2 R124.2
N$156: IC8.4(A:-IN) JP30.1
N$158: IC8.2(A:OUT) R125.1 R126.2
N$159: IC8.7(B:+IN) R127.2 R128.2
N$160: IC8.6(B:-IN) JP31.1
N$161: IC8.1(B:OUT) R129.1 R130.2
N$162: IC8.9(C:+IN) R131.2 R132.2
N$163: IC8.8(C:-IN) JP32.1
N$164: IC8.14(C:OUT) R133.1 R134.2
N$165: IC8.11(D:+IN) R135.2 R136.2
N$166: IC8.10(D:-IN) JP33.1
N$167: IC8.13(D:OUT) R137.1 R138.2
P1: R60.1 ; also sheet 1,3,4
P2: R116.1 ; also sheet 1,3,4
R1: R64.1 ; also sheet 1,3,4
R2: R120.1 ; also sheet 1,3,4
RXA1: D2.C R7.1 SV7.2
RXB1: D9.C R18.1 SV7.4
RXC1: D10.C R22.1 SV7.6
RXD1: D11.C R26.1 SV7.8
RXD2: D25.C R82.1 SV8.4
RXE1: D12.C R30.1 SV7.1
RXE2: D26.C R86.1 SV8.6
RXF1: D13.C R34.1 SV7.3
RXF2: D27.C R90.1 SV8.8
RXH1: D14.C R38.1 SV7.5
RXH2: D28.C R94.1 SV8.1
RXJ1: D15.C R42.1 SV7.7
RXJ2: D29.C R98.1 SV8.3
RXK1: D16.C R46.1 SV7.10
RXK2: D30.C R102.1 SV8.5
RXL1: D17.C R50.1 SV7.12
RXL2: D31.C R106.1 SV8.7
RXM1: D18.C R54.1 SV7.14
RXM2: D32.C R110.1 SV8.10
RXN1: D19.C R58.1 SV7.16
RXN2: D33.C R114.1 SV8.12
RXP1: D20.C R62.1 SV7.9
RXP2: D34.C R118.1 SV8.14
RXR1: D21.C R66.1 SV7.11
RXR2: D35.C R122.1 SV8.16
RXS1: D22.C R70.1 SV7.13
RXS2: D36.C R126.1 SV8.9
RXT2: D37.C R130.1 SV8.11
RXU1: D23.C R74.1 SV7.15
RXU2: D38.C R134.1 SV8.13
RXV1: D24.C R78.1 SV8.2
RXV2: D39.C R138.1 SV8.15
S1: R68.1 ; also sheet 1,3,4
S2: R124.1 ; also sheet 1,3,4
T2: R128.1 ; also sheet 1,3,4
THR: JP1.2 JP3.2 JP4.2 JP5.2 JP6.2 JP7.2 JP8.2 JP9.2 JP10.2 JP11.2 JP12.2 JP13.2 JP14.2 JP15.2 JP16.2 JP17.2 JP18.2 JP19.2 JP20.2 JP21.2 JP22.2 JP23.2 JP24.2 JP25.2 JP26.2 JP27.2 JP28.2 JP29.2 JP30.2 JP31.2 JP32.2 JP33.2 ; also sheet 4
U1: R72.1 ; also sheet 1,3,4
U2: R132.1 ; also sheet 1,3,4
V1: R76.1 ; also sheet 1,3,4
V2: R136.1 ; also sheet 1,3,4
V+: IC1.3(P:V+) IC2.3(P:V+) IC3.3(P:V+) IC4.3(P:V+) IC5.3(P:V+) IC6.3(P:V+) IC7.3(P:V+) IC8.3(P:V+) R6.2 R17.2 R21.2 R25.2 R29.2 R33.2 R37.2 R41.2 R45.2 R49.2 R53.2 R57.2 R61.2 R65.2 R69.2 R73.2 R77.2 R81.2 R85.2 R89.2 R93.2 R97.2 R101.2 R105.2 R109.2 R113.2 R117.2 R121.2 R125.2 R129.2 R133.2 R137.2 ; also sheet 4
V-: IC1.12(P:GND) IC2.12(P:GND) IC3.12(P:GND) IC4.12(P:GND) IC5.12(P:GND) IC6.12(P:GND) IC7.12(P:GND) IC8.12(P:GND) ; also sheet 4

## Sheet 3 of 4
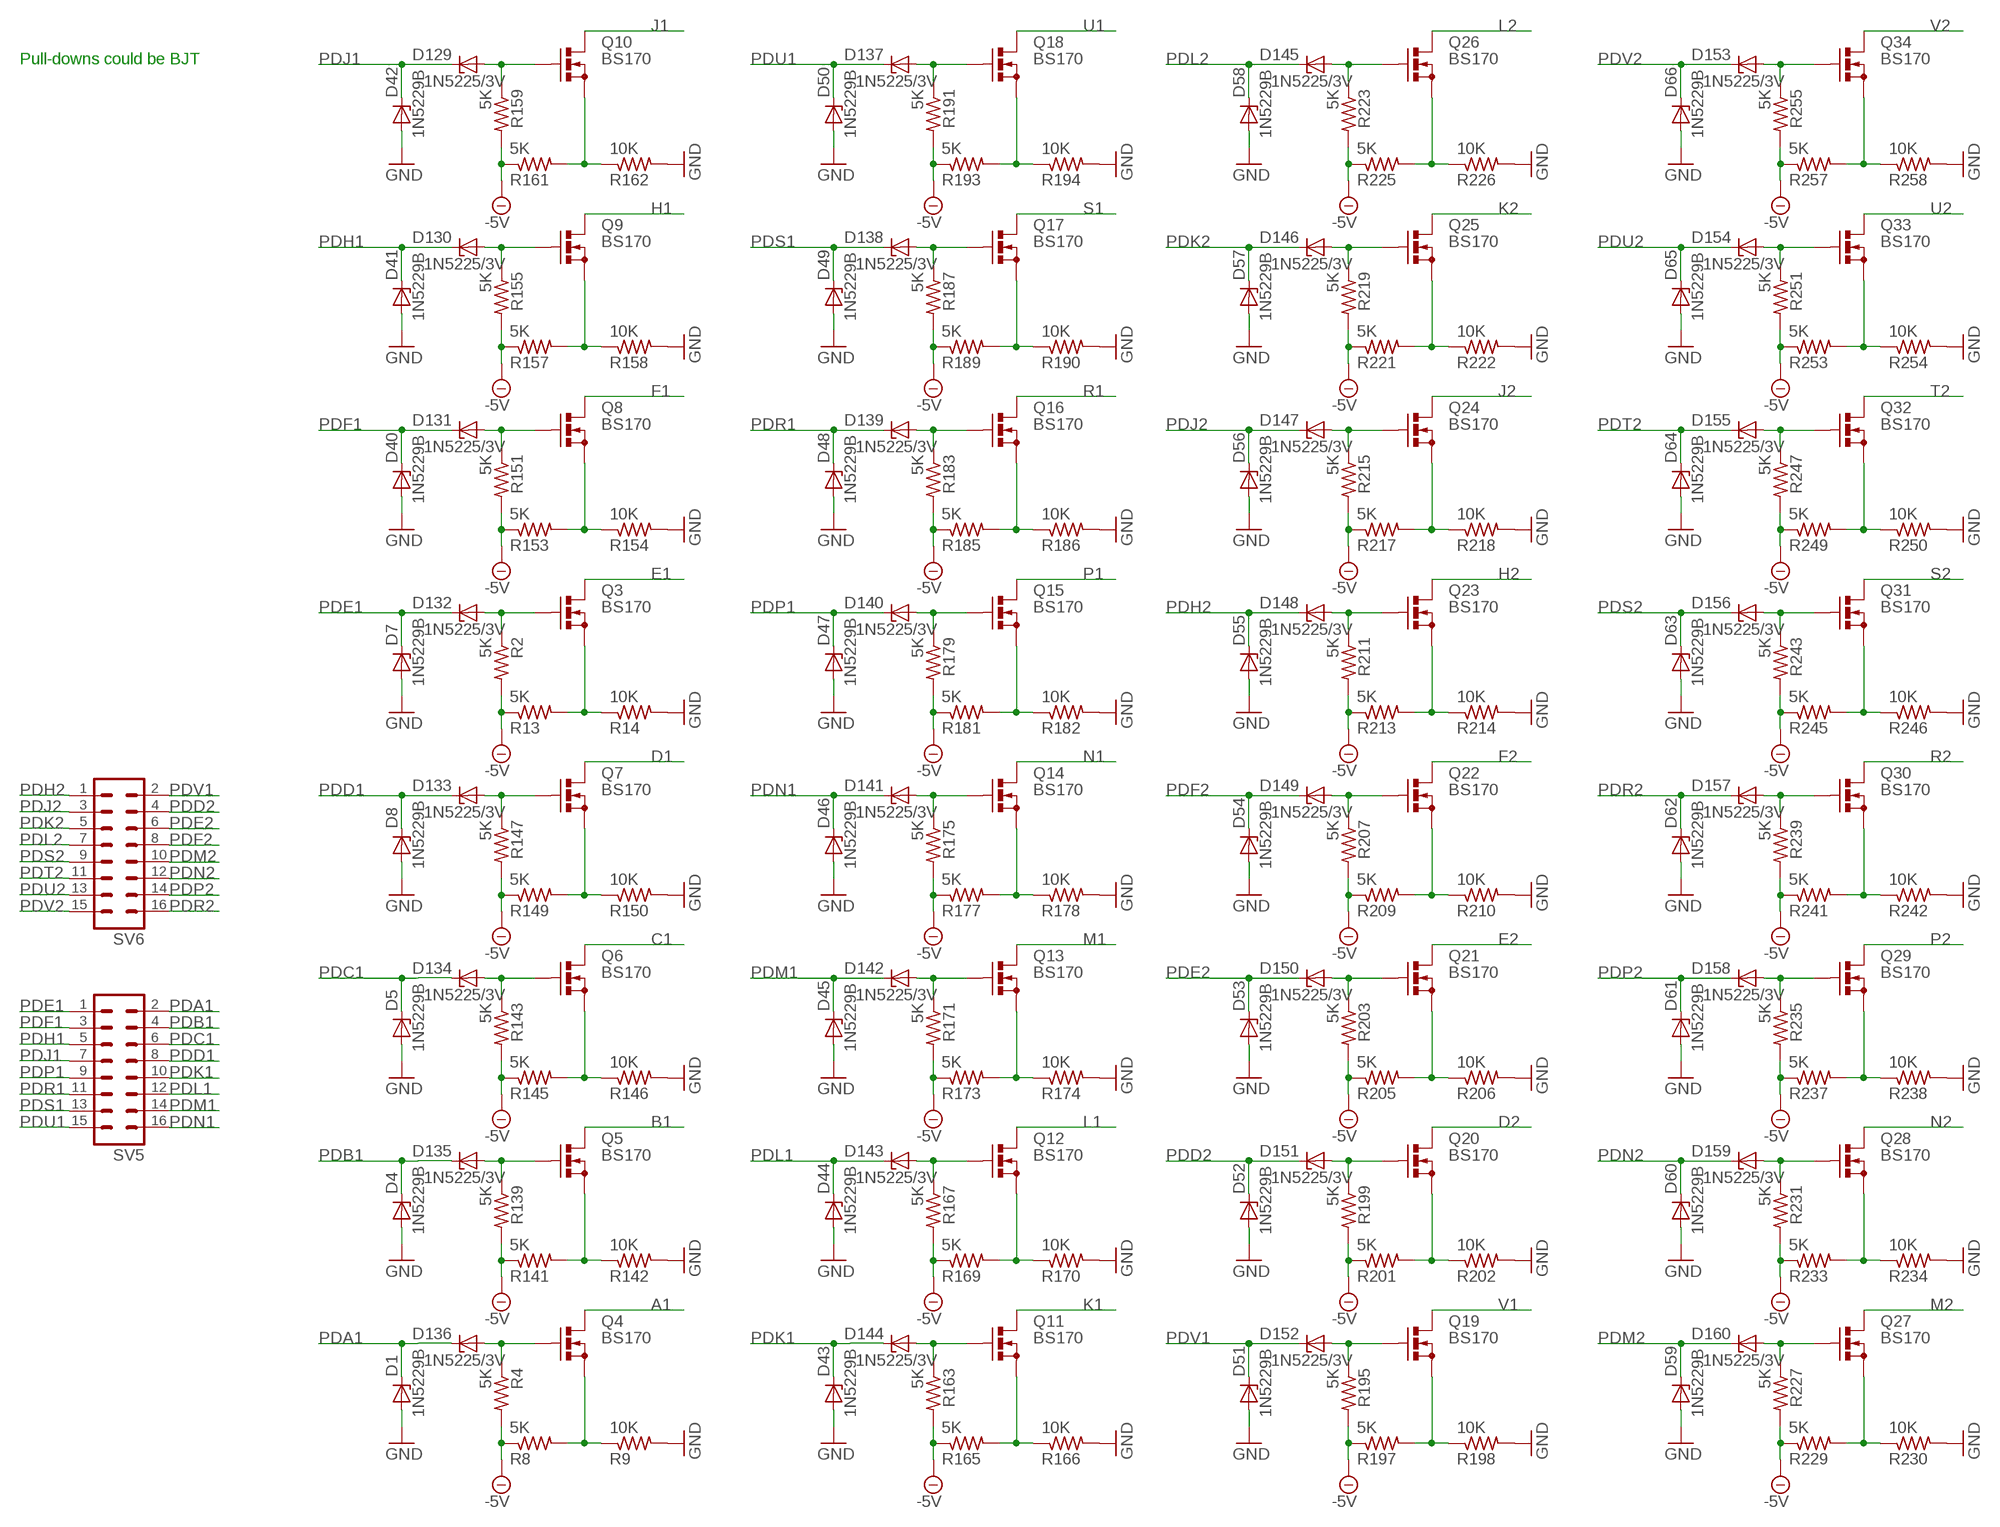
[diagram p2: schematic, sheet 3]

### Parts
D1  1N5229B  ZENER-DIODEZD-2.5  [ZDIO-2.5]
D4  1N5229B  ZENER-DIODEZD-2.5  [ZDIO-2.5]
D5  1N5229B  ZENER-DIODEZD-2.5  [ZDIO-2.5]
D7  1N5229B  ZENER-DIODEZD-2.5  [ZDIO-2.5]
D8  1N5229B  ZENER-DIODEZD-2.5  [ZDIO-2.5]
D40  1N5229B  ZENER-DIODEZD-2.5  [ZDIO-2.5]
D41  1N5229B  ZENER-DIODEZD-2.5  [ZDIO-2.5]
D42  1N5229B  ZENER-DIODEZD-2.5  [ZDIO-2.5]
D43  1N5229B  ZENER-DIODEZD-2.5  [ZDIO-2.5]
D44  1N5229B  ZENER-DIODEZD-2.5  [ZDIO-2.5]
D45  1N5229B  ZENER-DIODEZD-2.5  [ZDIO-2.5]
D46  1N5229B  ZENER-DIODEZD-2.5  [ZDIO-2.5]
D47  1N5229B  ZENER-DIODEZD-2.5  [ZDIO-2.5]
D48  1N5229B  ZENER-DIODEZD-2.5  [ZDIO-2.5]
D49  1N5229B  ZENER-DIODEZD-2.5  [ZDIO-2.5]
D50  1N5229B  ZENER-DIODEZD-2.5  [ZDIO-2.5]
D51  1N5229B  ZENER-DIODEZD-2.5  [ZDIO-2.5]
D52  1N5229B  ZENER-DIODEZD-2.5  [ZDIO-2.5]
D53  1N5229B  ZENER-DIODEZD-2.5  [ZDIO-2.5]
D54  1N5229B  ZENER-DIODEZD-2.5  [ZDIO-2.5]
D55  1N5229B  ZENER-DIODEZD-2.5  [ZDIO-2.5]
D56  1N5229B  ZENER-DIODEZD-2.5  [ZDIO-2.5]
D57  1N5229B  ZENER-DIODEZD-2.5  [ZDIO-2.5]
D58  1N5229B  ZENER-DIODEZD-2.5  [ZDIO-2.5]
D59  1N5229B  ZENER-DIODEZD-2.5  [ZDIO-2.5]
D60  1N5229B  ZENER-DIODEZD-2.5  [ZDIO-2.5]
D61  1N5229B  ZENER-DIODEZD-2.5  [ZDIO-2.5]
D62  1N5229B  ZENER-DIODEZD-2.5  [ZDIO-2.5]
D63  1N5229B  ZENER-DIODEZD-2.5  [ZDIO-2.5]
D64  1N5229B  ZENER-DIODEZD-2.5  [ZDIO-2.5]
D65  1N5229B  ZENER-DIODEZD-2.5  [ZDIO-2.5]
D66  1N5229B  ZENER-DIODEZD-2.5  [ZDIO-2.5]
D129  1N5225/3V  ZENER-DIODEZD-2.5  [ZDIO-2.5]
D130  1N5225/3V  ZENER-DIODEZD-2.5  [ZDIO-2.5]
D131  1N5225/3V  ZENER-DIODEZD-2.5  [ZDIO-2.5]
D132  1N5225/3V  ZENER-DIODEZD-2.5  [ZDIO-2.5]
D133  1N5225/3V  ZENER-DIODEZD-2.5  [ZDIO-2.5]
D134  1N5225/3V  ZENER-DIODEZD-2.5  [ZDIO-2.5]
D135  1N5225/3V  ZENER-DIODEZD-2.5  [ZDIO-2.5]
D136  1N5225/3V  ZENER-DIODEZD-2.5  [ZDIO-2.5]
D137  1N5225/3V  ZENER-DIODEZD-2.5  [ZDIO-2.5]
D138  1N5225/3V  ZENER-DIODEZD-2.5  [ZDIO-2.5]
D139  1N5225/3V  ZENER-DIODEZD-2.5  [ZDIO-2.5]
D140  1N5225/3V  ZENER-DIODEZD-2.5  [ZDIO-2.5]
D141  1N5225/3V  ZENER-DIODEZD-2.5  [ZDIO-2.5]
D142  1N5225/3V  ZENER-DIODEZD-2.5  [ZDIO-2.5]
D143  1N5225/3V  ZENER-DIODEZD-2.5  [ZDIO-2.5]
D144  1N5225/3V  ZENER-DIODEZD-2.5  [ZDIO-2.5]
D145  1N5225/3V  ZENER-DIODEZD-2.5  [ZDIO-2.5]
D146  1N5225/3V  ZENER-DIODEZD-2.5  [ZDIO-2.5]
D147  1N5225/3V  ZENER-DIODEZD-2.5  [ZDIO-2.5]
D148  1N5225/3V  ZENER-DIODEZD-2.5  [ZDIO-2.5]
D149  1N5225/3V  ZENER-DIODEZD-2.5  [ZDIO-2.5]
D150  1N5225/3V  ZENER-DIODEZD-2.5  [ZDIO-2.5]
D151  1N5225/3V  ZENER-DIODEZD-2.5  [ZDIO-2.5]
D152  1N5225/3V  ZENER-DIODEZD-2.5  [ZDIO-2.5]
D153  1N5225/3V  ZENER-DIODEZD-2.5  [ZDIO-2.5]
D154  1N5225/3V  ZENER-DIODEZD-2.5  [ZDIO-2.5]
D155  1N5225/3V  ZENER-DIODEZD-2.5  [ZDIO-2.5]
D156  1N5225/3V  ZENER-DIODEZD-2.5  [ZDIO-2.5]
D157  1N5225/3V  ZENER-DIODEZD-2.5  [ZDIO-2.5]
D158  1N5225/3V  ZENER-DIODEZD-2.5  [ZDIO-2.5]
D159  1N5225/3V  ZENER-DIODEZD-2.5  [ZDIO-2.5]
D160  1N5225/3V  ZENER-DIODEZD-2.5  [ZDIO-2.5]
Q3  BS170  [SOT54E]
Q4  BS170  [SOT54E]
Q5  BS170  [SOT54E]
Q6  BS170  [SOT54E]
Q7  BS170  [SOT54E]
Q8  BS170  [SOT54E]
Q9  BS170  [SOT54E]
Q10  BS170  [SOT54E]
Q11  BS170  [SOT54E]
Q12  BS170  [SOT54E]
Q13  BS170  [SOT54E]
Q14  BS170  [SOT54E]
Q15  BS170  [SOT54E]
Q16  BS170  [SOT54E]
Q17  BS170  [SOT54E]
Q18  BS170  [SOT54E]
Q19  BS170  [SOT54E]
Q20  BS170  [SOT54E]
Q21  BS170  [SOT54E]
Q22  BS170  [SOT54E]
Q23  BS170  [SOT54E]
Q24  BS170  [SOT54E]
Q25  BS170  [SOT54E]
Q26  BS170  [SOT54E]
Q27  BS170  [SOT54E]
Q28  BS170  [SOT54E]
Q29  BS170  [SOT54E]
Q30  BS170  [SOT54E]
Q31  BS170  [SOT54E]
Q32  BS170  [SOT54E]
Q33  BS170  [SOT54E]
Q34  BS170  [SOT54E]
R2  5K  R-US_0207/2V  [0207/2V]
R4  5K  R-US_0207/2V  [0207/2V]
R8  5K  R-US_0207/2V  [0207/2V]
R9  10K  R-US_0207/2V  [0207/2V]
R13  5K  R-US_0207/2V  [0207/2V]
R14  10K  R-US_0207/2V  [0207/2V]
R139  5K  R-US_0207/2V  [0207/2V]
R141  5K  R-US_0207/2V  [0207/2V]
R142  10K  R-US_0207/2V  [0207/2V]
R143  5K  R-US_0207/2V  [0207/2V]
R145  5K  R-US_0207/2V  [0207/2V]
R146  10K  R-US_0207/2V  [0207/2V]
R147  5K  R-US_0207/2V  [0207/2V]
R149  5K  R-US_0207/2V  [0207/2V]
R150  10K  R-US_0207/2V  [0207/2V]
R151  5K  R-US_0207/2V  [0207/2V]
R153  5K  R-US_0207/2V  [0207/2V]
R154  10K  R-US_0207/2V  [0207/2V]
R155  5K  R-US_0207/2V  [0207/2V]
R157  5K  R-US_0207/2V  [0207/2V]
R158  10K  R-US_0207/2V  [0207/2V]
R159  5K  R-US_0207/2V  [0207/2V]
R161  5K  R-US_0207/2V  [0207/2V]
R162  10K  R-US_0207/2V  [0207/2V]
R163  5K  R-US_0207/2V  [0207/2V]
R165  5K  R-US_0207/2V  [0207/2V]
R166  10K  R-US_0207/2V  [0207/2V]
R167  5K  R-US_0207/2V  [0207/2V]
R169  5K  R-US_0207/2V  [0207/2V]
R170  10K  R-US_0207/2V  [0207/2V]
R171  5K  R-US_0207/2V  [0207/2V]
R173  5K  R-US_0207/2V  [0207/2V]
R174  10K  R-US_0207/2V  [0207/2V]
R175  5K  R-US_0207/2V  [0207/2V]
R177  5K  R-US_0207/2V  [0207/2V]
R178  10K  R-US_0207/2V  [0207/2V]
R179  5K  R-US_0207/2V  [0207/2V]
R181  5K  R-US_0207/2V  [0207/2V]
R182  10K  R-US_0207/2V  [0207/2V]
R183  5K  R-US_0207/2V  [0207/2V]
R185  5K  R-US_0207/2V  [0207/2V]
R186  10K  R-US_0207/2V  [0207/2V]
R187  5K  R-US_0207/2V  [0207/2V]
R189  5K  R-US_0207/2V  [0207/2V]
R190  10K  R-US_0207/2V  [0207/2V]
R191  5K  R-US_0207/2V  [0207/2V]
R193  5K  R-US_0207/2V  [0207/2V]
R194  10K  R-US_0207/2V  [0207/2V]
R195  5K  R-US_0207/2V  [0207/2V]
R197  5K  R-US_0207/2V  [0207/2V]
R198  10K  R-US_0207/2V  [0207/2V]
R199  5K  R-US_0207/2V  [0207/2V]
R201  5K  R-US_0207/2V  [0207/2V]
R202  10K  R-US_0207/2V  [0207/2V]
R203  5K  R-US_0207/2V  [0207/2V]
R205  5K  R-US_0207/2V  [0207/2V]
R206  10K  R-US_0207/2V  [0207/2V]
R207  5K  R-US_0207/2V  [0207/2V]
R209  5K  R-US_0207/2V  [0207/2V]
R210  10K  R-US_0207/2V  [0207/2V]
R211  5K  R-US_0207/2V  [0207/2V]
R213  5K  R-US_0207/2V  [0207/2V]
R214  10K  R-US_0207/2V  [0207/2V]
R215  5K  R-US_0207/2V  [0207/2V]
R217  5K  R-US_0207/2V  [0207/2V]
R218  10K  R-US_0207/2V  [0207/2V]
R219  5K  R-US_0207/2V  [0207/2V]
R221  5K  R-US_0207/2V  [0207/2V]
R222  10K  R-US_0207/2V  [0207/2V]
R223  5K  R-US_0207/2V  [0207/2V]
R225  5K  R-US_0207/2V  [0207/2V]
R226  10K  R-US_0207/2V  [0207/2V]
R227  5K  R-US_0207/2V  [0207/2V]
R229  5K  R-US_0207/2V  [0207/2V]
R230  10K  R-US_0207/2V  [0207/2V]
R231  5K  R-US_0207/2V  [0207/2V]
R233  5K  R-US_0207/2V  [0207/2V]
R234  10K  R-US_0207/2V  [0207/2V]
R235  5K  R-US_0207/2V  [0207/2V]
R237  5K  R-US_0207/2V  [0207/2V]
R238  10K  R-US_0207/2V  [0207/2V]
R239  5K  R-US_0207/2V  [0207/2V]
R241  5K  R-US_0207/2V  [0207/2V]
R242  10K  R-US_0207/2V  [0207/2V]
R243  5K  R-US_0207/2V  [0207/2V]
R245  5K  R-US_0207/2V  [0207/2V]
R246  10K  R-US_0207/2V  [0207/2V]
R247  5K  R-US_0207/2V  [0207/2V]
R249  5K  R-US_0207/2V  [0207/2V]
R250  10K  R-US_0207/2V  [0207/2V]
R251  5K  R-US_0207/2V  [0207/2V]
R253  5K  R-US_0207/2V  [0207/2V]
R254  10K  R-US_0207/2V  [0207/2V]
R255  5K  R-US_0207/2V  [0207/2V]
R257  5K  R-US_0207/2V  [0207/2V]
R258  10K  R-US_0207/2V  [0207/2V]
SV5  MA08-2  [MA08-2]
SV6  MA08-2  [MA08-2]

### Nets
-5V: R2.2 R4.2 R8.1 R13.1 R139.2 R141.1 R143.2 R145.1 R147.2 R149.1 R151.2 R153.1 R155.2 R157.1 R159.2 R161.1 R163.2 R165.1 R167.2 R169.1 R171.2 R173.1 R175.2 R177.1 R179.2 R181.1 R183.2 R185.1 R187.2 R189.1 R191.2 R193.1 R195.2 R197.1 R199.2 R201.1 R203.2 R205.1 R207.2 R209.1 R211.2 R213.1 R215.2 R217.1 R219.2 R221.1 R223.2 R225.1 R227.2 R229.1 R231.2 R233.1 R235.2 R237.1 R239.2 R241.1 R243.2 R245.1 R247.2 R249.1 R251.2 R253.1 R255.2 R257.1 ; also sheet 4
A1: Q4.D ; also sheet 1,2,4
B1: Q5.D ; also sheet 1,2,4
C1: Q6.D ; also sheet 1,2,4
D1: Q7.D ; also sheet 1,2,4
D2: Q20.D ; also sheet 1,2,4
E1: Q3.D ; also sheet 1,2,4
E2: Q21.D ; also sheet 1,2,4
F1: Q8.D ; also sheet 1,2,4
F2: Q22.D ; also sheet 1,2,4
GND: D1.A D4.A D5.A D7.A D8.A D40.A D41.A D42.A D43.A D44.A D45.A D46.A D47.A D48.A D49.A D50.A D51.A D52.A D53.A D54.A D55.A D56.A D57.A D58.A D59.A D60.A D61.A D62.A D63.A D64.A D65.A D66.A R9.2 R14.2 R142.2 R146.2 R150.2 R154.2 R158.2 R162.2 R166.2 R170.2 R174.2 R178.2 R182.2 R186.2 R190.2 R194.2 R198.2 R202.2 R206.2 R210.2 R214.2 R218.2 R222.2 R226.2 R230.2 R234.2 R238.2 R242.2 R246.2 R250.2 R254.2 R258.2 ; also sheet 1,2,4
H1: Q9.D ; also sheet 1,2,4
H2: Q23.D ; also sheet 1,2,4
J1: Q10.D ; also sheet 1,2,4
J2: Q24.D ; also sheet 1,2,4
K1: Q11.D ; also sheet 1,2,4
K2: Q25.D ; also sheet 1,2,4
L1: Q12.D ; also sheet 1,2,4
L2: Q26.D ; also sheet 1,2,4
M1: Q13.D ; also sheet 1,2,4
M2: Q27.D ; also sheet 1,2,4
N1: Q14.D ; also sheet 1,2,4
N2: Q28.D ; also sheet 1,2,4
N$4: D132.A Q3.G R2.1
N$7: D136.A Q4.G R4.1
N$8: Q4.S R8.2 R9.1
N$12: D135.A Q5.G R139.1
N$15: Q5.S R141.2 R142.1
N$16: Q3.S R13.2 R14.1
N$177: D134.A Q6.G R143.1
N$178: Q6.S R145.2 R146.1
N$181: D133.A Q7.G R147.1
N$182: Q7.S R149.2 R150.1
N$186: D131.A Q8.G R151.1
N$187: Q8.S R153.2 R154.1
N$190: D130.A Q9.G R155.1
N$191: Q9.S R157.2 R158.1
N$194: D129.A Q10.G R159.1
N$195: Q10.S R161.2 R162.1
N$198: D144.A Q11.G R163.1
N$199: Q11.S R165.2 R166.1
N$202: D143.A Q12.G R167.1
N$203: Q12.S R169.2 R170.1
N$206: D142.A Q13.G R171.1
N$207: Q13.S R173.2 R174.1
N$210: D141.A Q14.G R175.1
N$211: Q14.S R177.2 R178.1
N$214: D140.A Q15.G R179.1
N$215: Q15.S R181.2 R182.1
N$218: D139.A Q16.G R183.1
N$219: Q16.S R185.2 R186.1
N$222: D138.A Q17.G R187.1
N$223: Q17.S R189.2 R190.1
N$226: D137.A Q18.G R191.1
N$227: Q18.S R193.2 R194.1
N$230: D152.A Q19.G R195.1
N$231: Q19.S R197.2 R198.1
N$234: D151.A Q20.G R199.1
N$235: Q20.S R201.2 R202.1
N$238: D150.A Q21.G R203.1
N$239: Q21.S R205.2 R206.1
N$242: D149.A Q22.G R207.1
N$243: Q22.S R209.2 R210.1
N$246: D148.A Q23.G R211.1
N$247: Q23.S R213.2 R214.1
N$250: D147.A Q24.G R215.1
N$251: Q24.S R217.2 R218.1
N$254: D146.A Q25.G R219.1
N$255: Q25.S R221.2 R222.1
N$258: D145.A Q26.G R223.1
N$259: Q26.S R225.2 R226.1
N$262: D160.A Q27.G R227.1
N$263: Q27.S R229.2 R230.1
N$266: D159.A Q28.G R231.1
N$267: Q28.S R233.2 R234.1
N$270: D158.A Q29.G R235.1
N$271: Q29.S R237.2 R238.1
N$274: D157.A Q30.G R239.1
N$275: Q30.S R241.2 R242.1
N$278: D156.A Q31.G R243.1
N$279: Q31.S R245.2 R246.1
N$282: D155.A Q32.G R247.1
N$283: Q32.S R249.2 R250.1
N$286: D154.A Q33.G R251.1
N$287: Q33.S R253.2 R254.1
N$290: D153.A Q34.G R255.1
N$291: Q34.S R257.2 R258.1
P1: Q15.D ; also sheet 1,2,4
P2: Q29.D ; also sheet 1,2,4
PDA1: D1.C D136.C SV5.2
PDB1: D4.C D135.C SV5.4
PDC1: D5.C D134.C SV5.6
PDD1: D8.C D133.C SV5.8
PDD2: D52.C D151.C SV6.4
PDE1: D7.C D132.C SV5.1
PDE2: D53.C D150.C SV6.6
PDF1: D40.C D131.C SV5.3
PDF2: D54.C D149.C SV6.8
PDH1: D41.C D130.C SV5.5
PDH2: D55.C D148.C SV6.1
PDJ1: D42.C D129.C SV5.7
PDJ2: D56.C D147.C SV6.3
PDK1: D43.C D144.C SV5.10
PDK2: D57.C D146.C SV6.5
PDL1: D44.C D143.C SV5.12
PDL2: D58.C D145.C SV6.7
PDM1: D45.C D142.C SV5.14
PDM2: D59.C D160.C SV6.10
PDN1: D46.C D141.C SV5.16
PDN2: D60.C D159.C SV6.12
PDP1: D47.C D140.C SV5.9
PDP2: D61.C D158.C SV6.14
PDR1: D48.C D139.C SV5.11
PDR2: D62.C D157.C SV6.16
PDS1: D49.C D138.C SV5.13
PDS2: D63.C D156.C SV6.9
PDT2: D64.C D155.C SV6.11
PDU1: D50.C D137.C SV5.15
PDU2: D65.C D154.C SV6.13
PDV1: D51.C D152.C SV6.2
PDV2: D66.C D153.C SV6.15
R1: Q16.D ; also sheet 1,2,4
R2: Q30.D ; also sheet 1,2,4
S1: Q17.D ; also sheet 1,2,4
S2: Q31.D ; also sheet 1,2,4
T2: Q32.D ; also sheet 1,2,4
U1: Q18.D ; also sheet 1,2,4
U2: Q33.D ; also sheet 1,2,4
V1: Q19.D ; also sheet 1,2,4
V2: Q34.D ; also sheet 1,2,4

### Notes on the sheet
- Pull-downs could be BJT

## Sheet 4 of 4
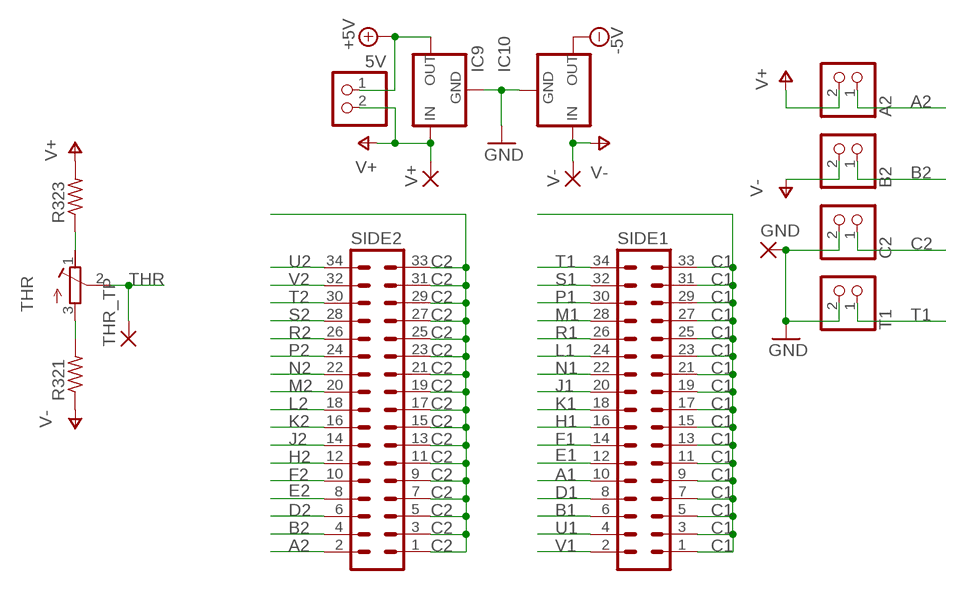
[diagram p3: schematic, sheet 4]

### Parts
5V  PINHD-1X2  [1X02]
A2  PINHD-1X2  [1X02]
B2  PINHD-1X2  [1X02]
C2  PINHD-1X2  [1X02]
GND  1,6/0,9  [1,6/0,9]
IC9  78XXL  [78XXL]
IC10  79XXL  [79XXL]
R321  R-US_0207/2V  [0207/2V]
R323  R-US_0207/2V  [0207/2V]
SIDE1  MA17-2  [MA17-2]
SIDE2  MA17-2  [MA17-2]
T1  PINHD-1X2  [1X02]
THR  R-TRIMMT18  [RTRIMT18]
THR_TP  1,6/0,9  [1,6/0,9]
V+  1,6/0,9  [1,6/0,9]
V-  1,6/0,9  [1,6/0,9]

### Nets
+5V: 5V.1 IC9.OUT ; also sheet 1
-5V: IC10.OUT ; also sheet 3
A1: SIDE1.10 ; also sheet 1,2,3
A2: A2.1 SIDE2.2
B1: SIDE1.6 ; also sheet 1,2,3
B2: B2.1 SIDE2.4
C1: SIDE1.1 SIDE1.3 SIDE1.5 SIDE1.7 SIDE1.9 SIDE1.11 SIDE1.13 SIDE1.15 SIDE1.17 SIDE1.19 SIDE1.21 SIDE1.23 SIDE1.25 SIDE1.27 SIDE1.29 SIDE1.31 SIDE1.33 ; also sheet 1,2,3
C2: C2.1 SIDE2.1 SIDE2.3 SIDE2.5 SIDE2.7 SIDE2.9 SIDE2.11 SIDE2.13 SIDE2.15 SIDE2.17 SIDE2.19 SIDE2.21 SIDE2.23 SIDE2.25 SIDE2.27 SIDE2.29 SIDE2.31 SIDE2.33
D1: SIDE1.8 ; also sheet 1,2,3
D2: SIDE2.6 ; also sheet 1,2,3
E1: SIDE1.12 ; also sheet 1,2,3
E2: SIDE2.8 ; also sheet 1,2,3
F1: SIDE1.14 ; also sheet 1,2,3
F2: SIDE2.10 ; also sheet 1,2,3
GND: C2.2 GND.1(P) IC9.GND IC10.GND T1.2 ; also sheet 1,2,3
H1: SIDE1.16 ; also sheet 1,2,3
H2: SIDE2.12 ; also sheet 1,2,3
J1: SIDE1.20 ; also sheet 1,2,3
J2: SIDE2.14 ; also sheet 1,2,3
K1: SIDE1.18 ; also sheet 1,2,3
K2: SIDE2.16 ; also sheet 1,2,3
L1: SIDE1.24 ; also sheet 1,2,3
L2: SIDE2.18 ; also sheet 1,2,3
M1: SIDE1.28 ; also sheet 1,2,3
M2: SIDE2.20 ; also sheet 1,2,3
N1: SIDE1.22 ; also sheet 1,2,3
N2: SIDE2.22 ; also sheet 1,2,3
N$2: R321.2 THR.3(E)
N$3: R323.1 THR.1(A)
P1: SIDE1.30 ; also sheet 1,2,3
P2: SIDE2.24 ; also sheet 1,2,3
R1: SIDE1.26 ; also sheet 1,2,3
R2: SIDE2.26 ; also sheet 1,2,3
S1: SIDE1.32 ; also sheet 1,2,3
S2: SIDE2.28 ; also sheet 1,2,3
T1: SIDE1.34 T1.1
T2: SIDE2.30 ; also sheet 1,2,3
THR: THR.2(S) THR_TP.1(P) ; also sheet 2
U1: SIDE1.4 ; also sheet 1,2,3
U2: SIDE2.34 ; also sheet 1,2,3
V1: SIDE1.2 ; also sheet 1,2,3
V2: SIDE2.32 ; also sheet 1,2,3
V+: 5V.2 A2.2 IC9.IN R323.2 V+.1(P) ; also sheet 2
V-: B2.2 IC10.IN R321.1 V-.1(P) ; also sheet 2

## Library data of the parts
5V A2 B2 C2 JP1 JP3-JP33 T1 = pinhead:PINHD-1X2: PIN HEADER
D1-D160 = diode:ZENER-DIODE: Z-Diode
GND THR_TP V+ V- = wirepad:1,6/0,9: THROUGH-HOLE PAD
IC1-IC8 = linear:LM339: Low Power Low Offset Voltage Quad Comparators with open collector; LM139/LM239/LM339/LM2901/LM3302
IC9 = v-reg:78XXL: VOLTAGE REGULATOR
IC10 = v-reg:79XXL: VOLTAGE REGULATOR
Q1 Q3-Q35 Q37 Q39 Q41 Q43 Q45 Q47 Q49 Q51 Q53 Q55 Q57 Q59 Q61 Q63 Q65 Q67 Q69 Q71 Q73 Q75 Q77 Q79 Q81 Q83 Q85 Q87 Q89 Q91 Q93 Q95 = transistor-small-signal:BS170: N-CHANNEL MOS FET
Q2 Q36 Q38 Q40 Q42 Q44 Q46 Q48 Q50 Q52 Q54 Q56 Q58 Q60 Q62 Q64 Q66 Q68 Q70 Q72 Q74 Q76 Q78 Q80 Q82 Q84 Q86 Q88 Q90 Q92 Q94 Q96 = transistor-small-signal:BS250: P-CHANNEL MOS FET
R1-R4 R6-R11 R13-R139 R141-R143 R145-R147 R149-R151 R153-R155 R157-R159 R161-R163 R165-R167 R169-R171 R173-R175 R177-R179 R181-R183 R185-R187 R189-R191 R193-R195 R197-R199 R201-R203 R205-R207 R209-R211 R213-R215 R217-R219 R221-R223 R225-R227 R229-R231 R233-R235 R237-R239 R241-R243 R245-R247 R249-R251 R253-R255 R257-R321 R323 = rcl:R-US_: RESISTOR, American symbol
SIDE1 SIDE2 = con-lstb:MA17-2: PIN HEADER
SV1-SV8 = con-lstb:MA08-2: PIN HEADER
THR = rcl:R-TRIMM: Trimm resistor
